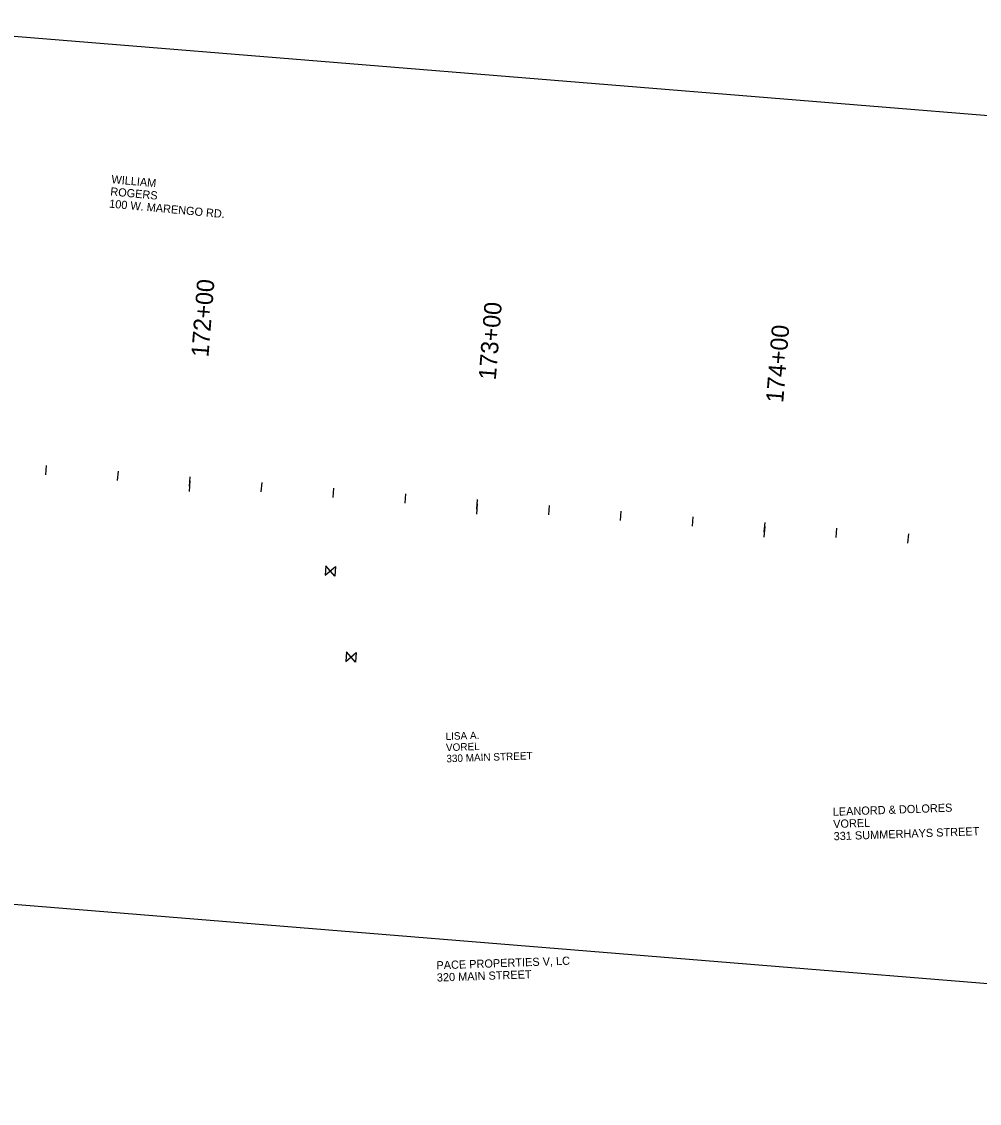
# Model space of a CAD drawing. Extents: x 20499788 to 20505371, y 7953467 to 7954209.
# Drawn here: x 20500853.2 to 20501185.4, y 7953750 to 7954125.3 of the extents above; entities that cross this region are included whole.
import ezdxf

# ---------------------------------------------------------------- set-up
doc = ezdxf.new("R2010")
doc.units = 0
for name, color, linetype in [('NamedBoundary', 7, 'Continuous'), ('Text', 7, 'Continuous'), ('TextAlignmentLrg', 7, 'Continuous'), ('TextAlignmentSml', 7, 'Continuous'), ('Utility-Water - alignment', 7, 'Continuous')]:
    doc.layers.add(name, color=color, linetype=linetype)

msp = doc.modelspace()

# ---------------------------------------------------------------- linework, layer by layer
at = {"layer": 'NamedBoundary'}
msp.add_lwpolyline([(20500786.55, 7954125.26), (20500762.22, 7953826.25), (20501699.61, 7953749.96), (20501723.94, 7954048.98)], close=True, dxfattribs=at)
at = {"layer": 'TextAlignmentLrg'}
for p, q in [((20500911.39, 7953964.08), (20500911.65, 7953967.34)), ((20501011.07, 7953956.16), (20501011.33, 7953959.42)), ((20501110.76, 7953948.24), (20501111.02, 7953951.5))]:
    msp.add_line(p, q, dxfattribs=at)
at = {"layer": 'TextAlignmentSml'}
for p, q in [((20500861.54, 7953968.04), (20500861.8, 7953971.31)), ((20500886.46, 7953966.06), (20500886.72, 7953969.33)), ((20500911.53, 7953965.91), (20500911.24, 7953962.25)), ((20500936.31, 7953962.1), (20500936.57, 7953965.36)), ((20500961.23, 7953960.12), (20500961.49, 7953963.38)), ((20500986.15, 7953958.14), (20500986.41, 7953961.4)), ((20501011.22, 7953957.99), (20501010.93, 7953954.33)), ((20501035.99, 7953954.18), (20501036.25, 7953957.44)), ((20501060.91, 7953952.2), (20501061.17, 7953955.46)), ((20501085.84, 7953950.22), (20501086.1, 7953953.48)), ((20501110.9, 7953950.07), (20501110.61, 7953946.41)), ((20501135.68, 7953946.26), (20501135.94, 7953949.52)), ((20501160.6, 7953944.27), (20501160.86, 7953947.54))]:
    msp.add_line(p, q, dxfattribs=at)
at = {"layer": 'Utility-Water - alignment'}
for points in [[(20500958.71, 7953936.49), (20500958.44, 7953933.17), (20500962.03, 7953936.23), (20500961.77, 7953932.91)], [(20500965.87, 7953906.63), (20500965.6, 7953903.31), (20500969.19, 7953906.37), (20500968.92, 7953903.05)]]:
    msp.add_lwpolyline(points, close=True, dxfattribs=at)

# ---------------------------------------------------------------- texts
at = {"layer": 'Text'}
for s, height, rotation, p in [('WILLIAM', 2.835, 354.7645, (20500884.22, 7954069.22)), ('ROGERS', 2.835, 354.7645, (20500883.84, 7954064.98)), ('100 W. MARENGO RD.', 2.8346, 354.7645, (20500883.45, 7954060.75)), ('LISA A. ', 2.58, 2.0248, (20501000.27, 7953876.02)), ('VOREL', 2.58, 2.0248, (20501000.4, 7953872.15)), ('330 MAIN STREET', 2.5802, 2.0248, (20501000.54, 7953868.28)), ('LEANORD & DOLORES', 2.8346, 2.0248, (20501134.57, 7953849.71)), ('VOREL', 2.835, 2.0248, (20501134.72, 7953845.47)), ('331 SUMMERHAYS STREET', 2.8346, 2.0248, (20501134.87, 7953841.22)), ('PACE PROPERTIES V, LC', 2.8346, 2.0248, (20500997.1, 7953796.44)), ('320 MAIN STREET', 2.8346, 2.0248, (20500997.25, 7953792.2))]:
    msp.add_text(s, height=height, rotation=rotation, dxfattribs=at).set_placement(p)
at = {"layer": 'TextAlignmentSml'}
for s, p in [('172+00', (20500917.95, 7954008.7)), ('173+00', (20501017.63, 7954000.78)), ('174+00', (20501117.32, 7953992.86))]:
    msp.add_text(s, height=6.012, rotation=85.4564, dxfattribs=at).set_placement(p)

doc.saveas('drawing.dxf')
